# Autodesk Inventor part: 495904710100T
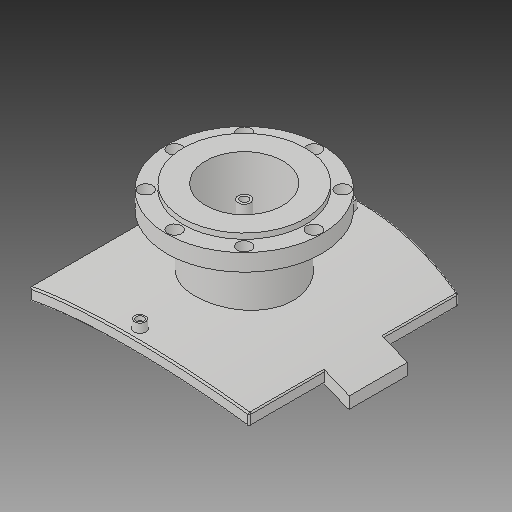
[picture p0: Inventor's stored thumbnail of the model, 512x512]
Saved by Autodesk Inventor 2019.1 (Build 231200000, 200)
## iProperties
Created: 2017-10
Part Number: 495904710100T
Material: Generic
Description: PLASSON FLANGED BRANCH SADDLE 450-800X100
Document SubType Name: Modeling
Designer: KIM
Mass: 2339.99 g
Surface Area: 3251.55 cm^2
Volume: 2339.99 cm^3
Density: 1 g/cm^3
Appearance: Default
Author: KIM
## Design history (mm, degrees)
derived "495904_495903.ipt"
feature "Solid1::495904_495903.ipt"
feature "Solid2::495904_495903.ipt"
tag "TaggingFeature1"
body "Solid1"
other parameters: "d1" = 15, "d2" = 283.5, "d4" = 0, "d6" = 75, "d7" = 0, "d12" = 425.6, "d13" = 14, "d14" = 135, "d16" = 5 deg, "d18" = 4, "d19" = 14, "d20" = 0, "d21" = 3, "d22" = 0, "d23" = 525, "d36" = 135, "d38" = 0, "d39" = 2, "d42" = 158, "d44" = 88, "d46" = 126.4, "d47" = 16, "d48" = 10.4, "d49" = 77, "d51" = 816, "d53" = 0, "d54" = 18, "d57" = 0, "d59" = 360 deg, "d61" = 22, "d63" = 0, "d67" = 15, "d68" = 55, "d70" = 0, "d71" = 2, "d72" = 315, "d_1" = 158, "B_" = 315, "x_" = 15, "D_" = 16, "t_" = 22, "s_" = 18
